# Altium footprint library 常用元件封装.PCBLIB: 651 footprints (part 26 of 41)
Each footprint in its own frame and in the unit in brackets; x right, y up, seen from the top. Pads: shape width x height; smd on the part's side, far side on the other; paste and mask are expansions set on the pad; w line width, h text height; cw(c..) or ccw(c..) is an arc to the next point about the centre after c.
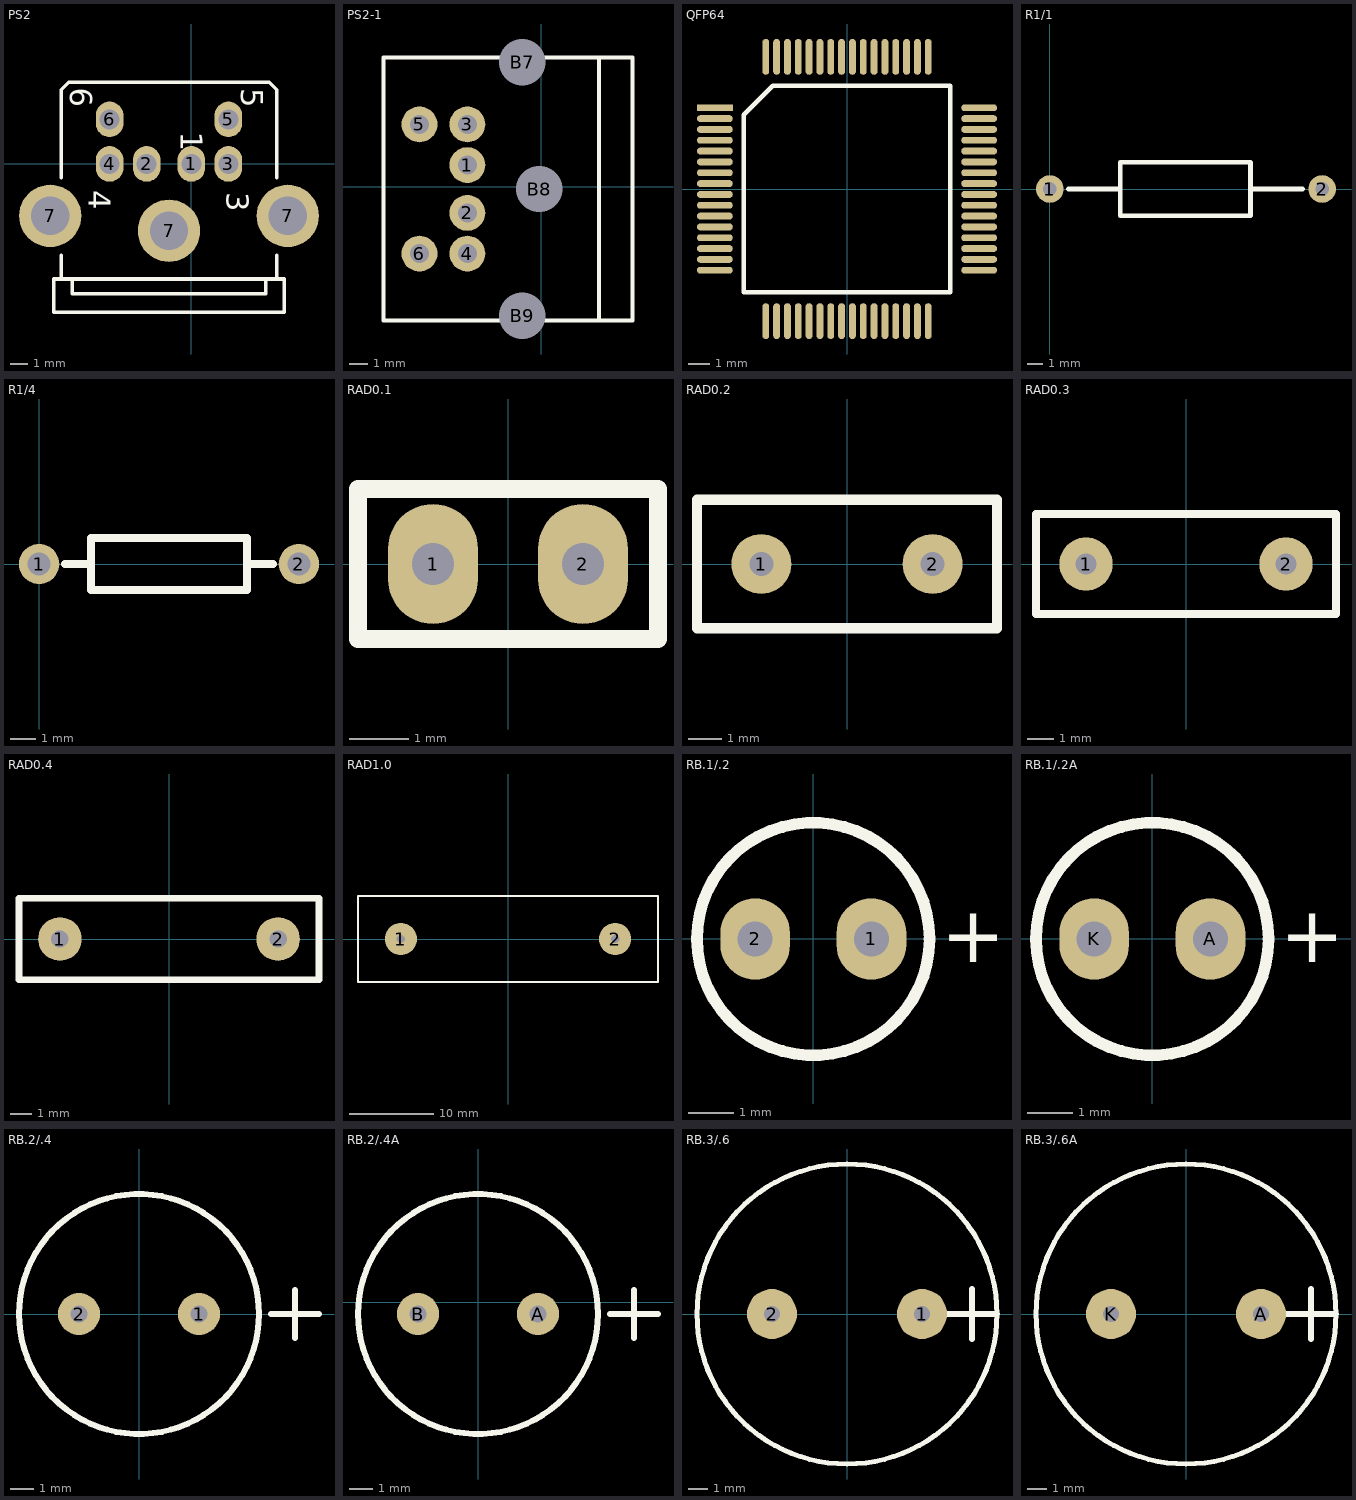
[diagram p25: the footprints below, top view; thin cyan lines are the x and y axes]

## PS2 [mil]
pads (9):
  oval 62x80 hole 45: 1(0,0) 2(-100,0) 3(83.33,0) 4(-183.33,0) 5(83.33,100) 6(-183.33,100)
  round 140 hole 86: 7(-316.67,-116.67) 7(-50,-150) 7(216.67,-116.67)
TopOverlay:
  lines w8: -291.67,-258.33 -291.67,-204.72 ; -291.67,-31.5 -291.67,166.67 -275,183.33 175,183.33 191.67,166.67 191.67,-31.5 ; 191.67,-258.33 191.67,-204.72 ; -266.67,-258.33 -308.33,-258.33 -308.33,-333.33 208.33,-333.33 208.33,-258.33 166.67,-258.33 ; -266.67,-258.33 -266.67,-291.67 166.67,-291.67 166.67,-258.33 ; -266.67,-258.33 166.67,-258.33
  text "5" at 112.57,169.43 h50
  text "6" at -271.43,170.76 h50
  text "4" at -230.1,-58.57 h50
  text "3" at 79.23,-63.9 h50
  text "1" at -23.43,72.1 h50

## PS2-1 [mil]
pads (9):
  round 75 hole 40: 1(-154,45) 2(-154,-55) 3(-154,130) 4(-154,-140) 5(-254,130) 6(-254,-140)
  round 75 hole 97: B7(-39,260) B8(-4,-5) B9(-39,-270)
TopOverlay:
  lines w8: 121,-280 121,270 ; -329,-280 191,-280 191,270 -329,270 -329,-280

## QFP64 [mm]
pads (64):
  rect 1.651x0.32 smd: 1(-6.1,3.75)
  oval 1.651x0.32 smd: 2(-6.1,3.25) 3(-6.1,2.75) 4(-6.1,2.25) 5(-6.1,1.75) 6(-6.1,1.25) 7(-6.1,0.75) 8(-6.1,0.25) 9(-6.1,-0.25) 10(-6.1,-0.75) 11(-6.1,-1.25) 12(-6.1,-1.75) 13(-6.1,-2.25) 14(-6.1,-2.75) 15(-6.1,-3.25) 16(-6.1,-3.75) 33(6.1,-3.75) 34(6.1,-3.25) 35(6.1,-2.75) 36(6.1,-2.25) 37(6.1,-1.75) 38(6.1,-1.25) 39(6.1,-0.75) 40(6.1,-0.25) 41(6.1,0.25) 42(6.1,0.75) 43(6.1,1.25) 44(6.1,1.75) 45(6.1,2.25) 46(6.1,2.75) 47(6.1,3.25) 48(6.1,3.75)
  oval 0.32x1.651 smd: 17(-3.75,-6.1) 18(-3.25,-6.1) 19(-2.75,-6.1) 20(-2.25,-6.1) 21(-1.75,-6.1) 22(-1.25,-6.1) 23(-0.75,-6.1) 24(-0.25,-6.1) 25(0.25,-6.1) 26(0.75,-6.1) 27(1.25,-6.1) 28(1.75,-6.1) 29(2.25,-6.1) 30(2.75,-6.1) 31(3.25,-6.1) 32(3.75,-6.1) 49(3.75,6.1) 50(3.25,6.1) 51(2.75,6.1) 52(2.25,6.1) 53(1.75,6.1) 54(1.25,6.1) 55(0.75,6.1) 56(0.25,6.1) 57(-0.25,6.1) 58(-0.75,6.1) 59(-1.25,6.1) 60(-1.75,6.1) 61(-2.25,6.1) 62(-2.75,6.1) 63(-3.25,6.1) 64(-3.75,6.1)
TopOverlay:
  lines w0.2: -4.765,-4.765 -4.765,3.43 -3.43,4.765 4.765,4.765 4.765,-4.765 -4.765,-4.765

## R1/1 [mm]
pads (2):
  round 1.8 hole 0.9: 1(0,0) 2(17.78,0)
TopOverlay:
  lines w0.305: 1.2,0 4.6,0 ; 4.6,-1.75 4.6,1.75 13.1,1.75 13.1,-1.75 4.7,-1.75 ; 13.1,0 16.5,0

## R1/4 [mil]
pads (2):
  round 62 hole 35.43: 1(0,0) 2(400,0)
TopOverlay:
  lines w12: 40,0 80,0 ; 320,0 360,0 ; 80,-40 320,-40 320,40 80,40 80,-40

## RAD0.1 [mil]
pads (2):
  oval 60x80 hole 28: 1(-50,0) 2(50,0)
TopOverlay:
  lines w12: -100,-50 100,-50 100,50 -100,50 -100,-50

## RAD0.2 [mil]
pads (2):
  round 70 hole 28: 1(-100,0) 2(100,0)
TopOverlay:
  lines w12: -175,-75 -175,75 175,75 175,-75 -175,-75

## RAD0.3 [mil]
pads (2):
  round 80 hole 32: 1(-150,0) 2(150,0)
TopOverlay:
  lines w12: -225,-75 -225,75 225,75 225,-75 -225,-75

## RAD0.4 [mil]
pads (2):
  round 80 hole 32: 1(-200,0) 2(200,0)
TopOverlay:
  lines w12: -275,-75 -275,75 275,75 275,-75 -275,-75

## RAD1.0 [mil]
pads (2):
  round 150 hole 39: 1(-500,0) 2(500,0)
TopOverlay:
  lines w10: -700,-200 -700,200 -500,200 500,200 700,200 700,-200 500,-200 -500,-200 -700,-200

## RB.1/.2 [mil]
pads (2):
  oval 60x70 hole 30: 1(50,0) 2(-50,0)
TopOverlay:
  circle w10: c0,0 r100
  text "+" at 110,-20 h48

## RB.1/.2A [mil]
pads (2):
  oval 60x70 hole 30: A(50,0) K(-50,0)
TopOverlay:
  circle w10: c0,0 r100
  text "+" at 110,-20 h48

## RB.2/.4 [mil]
pads (2):
  round 70 hole 28: 1(100,0) 2(-100,0)
TopOverlay:
  circle w10: c0,0 r200
  lines w10: 220,0 300,0 ; 260,-40 260,40

## RB.2/.4A [mil]
pads (2):
  round 70 hole 28: A(100,-20) B(-100,-20)
TopOverlay:
  circle w10: c0,-20 r200
  lines w10: 220,-20 300,-20 ; 260,-60 260,20

## RB.3/.6 [mil]
pads (2):
  round 100 hole 32: 1(150,0) 2(-150,0)
TopOverlay:
  circle w10: c0,0 r300
  lines w12: 200,0 300,0 ; 250,-50 250,50

## RB.3/.6A [mil]
pads (2):
  round 100 hole 32: A(150,0) K(-150,0)
TopOverlay:
  circle w10: c0,0 r300
  lines w12: 200,0 300,0 ; 250,-50 250,50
